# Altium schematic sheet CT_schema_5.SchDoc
size 396 x 205 mm
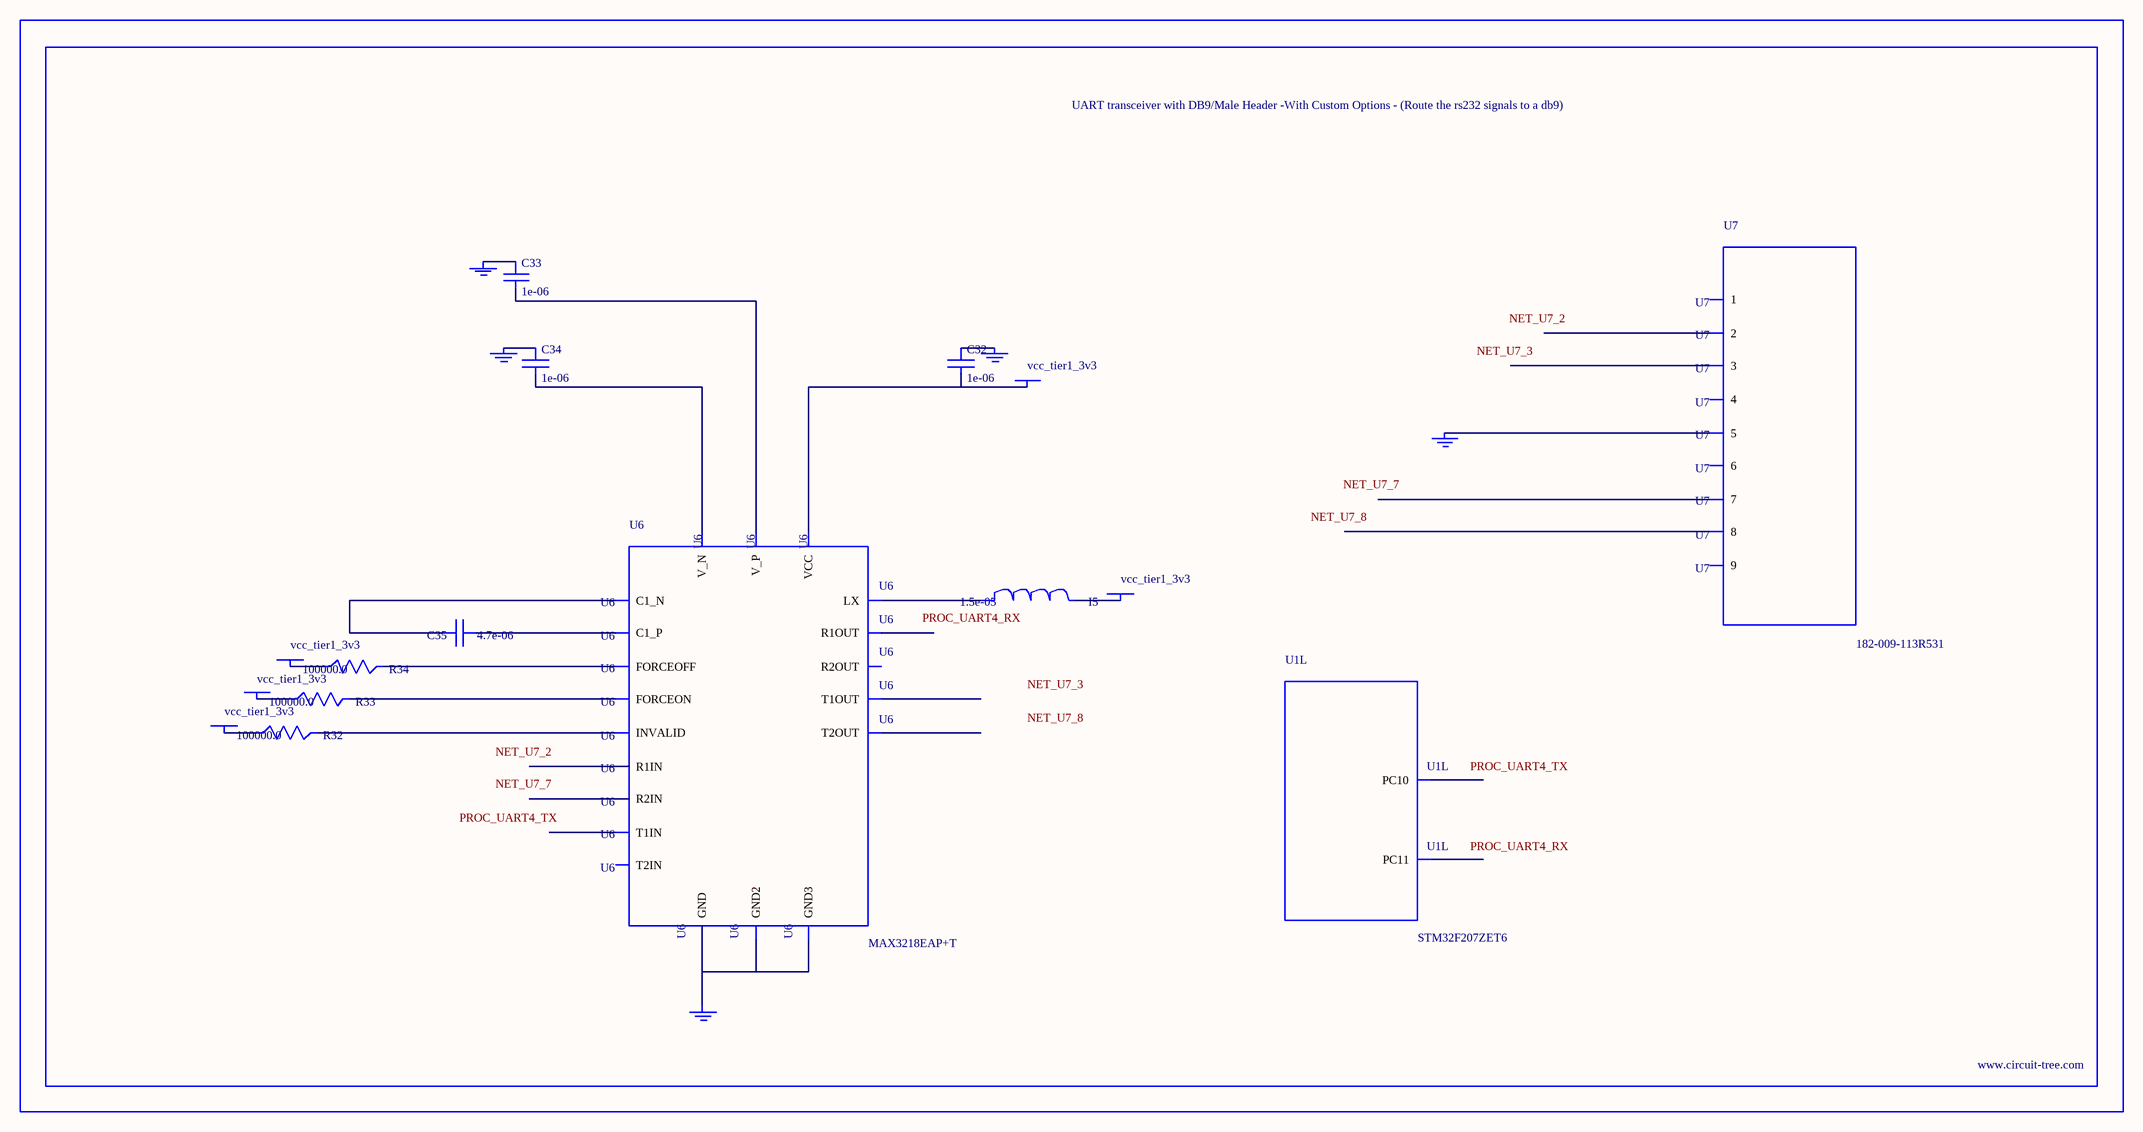
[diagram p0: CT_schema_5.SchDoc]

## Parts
BORDER4  (no value)
C32  1e-06  [C0603]
C33  1e-06  [C0603]
C34  1e-06  [C0603]
C35  4.7e-06  [C0805]
GND_INSTANCE_4_0  (no value)
GND_INSTANCE_4_1  (no value)
GND_INSTANCE_4_2  (no value)
GND_INSTANCE_4_3  (no value)
GND_INSTANCE_4_4  (no value)
I5  1.5e-05  [L1210]
POWER_INSTANCE_4_0  vcc_tier1_3v3
POWER_INSTANCE_4_1  vcc_tier1_3v3
POWER_INSTANCE_4_2  vcc_tier1_3v3
POWER_INSTANCE_4_3  vcc_tier1_3v3
POWER_INSTANCE_4_4  vcc_tier1_3v3
R32  100000.0  [R0603]
R33  100000.0  [R0603]
R34  100000.0  [R0603]
U1  STM32F207ZET6  [LQFP144]  (part L of 13)
U6  MAX3218EAP+T  [SSOP-20]
U7  182-009-113R531  [182-009-MALE]

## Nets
NetC32_1: C32.1 GND_INSTANCE_4_0.0(GND)
NetC32_2: C32.2 POWER_INSTANCE_4_4.0(PWR) U6.6(VCC)
NetC33_1: C33.1 GND_INSTANCE_4_2.0(GND)
NetC33_2: C33.2 U6.19(V_P)
NetC34_1: C34.1 GND_INSTANCE_4_1.0(GND)
NetC34_2: C34.2 U6.15(V_N)
NetC35_1: C35.1 U6.18(C1_P)
NetC35_2: C35.2 U6.16(C1_N)
NetGND_INSTANCE_4_3_0: GND_INSTANCE_4_3.0(GND) U6.5(GND) U6.17(GND2) U6.20(GND3)
NetGND_INSTANCE_4_4_0: GND_INSTANCE_4_4.0(GND) U7.5
NetI5_1: I5.1 U6.1(LX)
NetI5_2: I5.2 POWER_INSTANCE_4_0.0(PWR)
NetPOWER_INSTANCE_4_1_0: POWER_INSTANCE_4_1.0(PWR) R32.1
NetPOWER_INSTANCE_4_2_0: POWER_INSTANCE_4_2.0(PWR) R33.1
NetPOWER_INSTANCE_4_3_0: POWER_INSTANCE_4_3.0(PWR) R34.1
NetR32_2: R32.2 U6.2(INVALID)
NetR33_2: R33.2 U6.3(FORCEON)
NetR34_2: R34.2 U6.4(FORCEOFF)

Not connected (* = marked no-connect by the designer): U1 111(PC10) 112(PC11); U6 7(T1IN) 8(T2IN) 9(R1OUT) 10(R2OUT) 11(R2IN) 12(R1IN) 13(T2OUT) 14(T1OUT); U7 1 2 3 4 6 7 8 9

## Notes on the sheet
- Labels drawn without touching a wire or pin: NET_U7_2, NET_U7_3, NET_U7_7, NET_U7_8, PROC_UART4_RX, PROC_UART4_TX

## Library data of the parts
BORDER4 = BORDER_PAGE4
C32-C34 = C0603C105K3RACTU
C35 = C0805C475K4RACTU
GND_INSTANCE_4_0-GND_INSTANCE_4_4 = GND
I5 = L1210R150MDWIT
POWER_INSTANCE_4_0-POWER_INSTANCE_4_4 = PWR
R32-R34 = RC0603JR-07100KL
